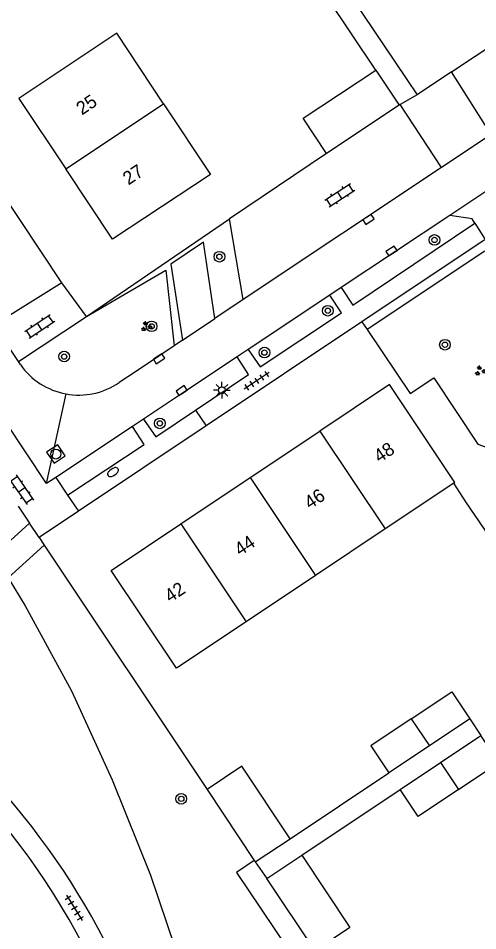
# Model space of a CAD drawing. Extents: x 137999 to 141000, y 397500 to 400501.
# Drawn here: x 138262.5 to 138297, y 399633.1 to 399701.6 of the extents above; entities that cross this region are included whole.
import ezdxf

# ---------------------------------------------------------------- set-up
doc = ezdxf.new("R2010")
doc.units = 0
for name, color, linetype in [('gg-afsc-erfafscheiding', 7, 'Continuous'), ('gg-afsc-muur', 7, 'Continuous'), ('gg-anno-huisnummerreeks BGT', 7, 'Continuous'), ('gg-bbg-bijgebouw', 7, 'Continuous'), ('gg-bbg-gedigitaliseerde bijgebouw', 7, 'Continuous'), ('gg-bbg-hoofdgebouw', 7, 'Continuous'), ('gg-bbg-tussenscheiding', 7, 'Continuous'), ('gg-knt-verharding', 7, 'Continuous'), ('gg-knt-verharding nz', 7, 'Continuous'), ('gt-grn-groengrens', 7, 'Continuous'), ('gt-grn-weggrens', 7, 'Continuous'), ('gt-symb-boom', 7, 'Continuous'), ('gt-symb-brandkraan', 7, 'Continuous'), ('gt-symb-groenvak', 7, 'Continuous'), ('gt-symb-klinker verharding', 7, 'Continuous'), ('gt-symb-kolk', 7, 'Continuous'), ('gt-symb-lichtmast', 7, 'Continuous'), ('gt-symb-rioolschacht', 7, 'Continuous'), ('gt-symb-tegel verharding', 7, 'Continuous')]:
    doc.layers.add(name, color=color, linetype=linetype)

# ---------------------------------------------------------------- blocks, each defined once
blk = doc.blocks.new('gt0-BOOM')
at = {"layer": 'gt-symb-boom'}
for radius in [0.4, 0.2]:
    blk.add_circle((0, 0), radius, dxfattribs=at)
blk = doc.blocks.new('gt0-TEG1')
at = {"layer": 'gt-symb-tegel verharding'}
for p, q in [((-1.125, 0), (1.125, 0)), ((-0.9, -0.25), (-0.9, 0.25)), ((-0.45, -0.25), (-0.45, 0.25)), ((0, -0.25), (0, 0.25)), ((0.45, -0.25), (0.45, 0.25)), ((0.9, -0.25), (0.9, 0.25))]:
    blk.add_line(p, q, dxfattribs=at)
blk = doc.blocks.new('gt0-KOLK')
at = {"layer": 'gt-symb-kolk'}
blk.add_lwpolyline([(0, 0), (0.375, 0), (0.375, 0.4), (-0.375, 0.4), (-0.375, 0), (0, 0)], dxfattribs=at)
blk = doc.blocks.new('gt0-KL1')
at = {"layer": 'gt-symb-klinker verharding'}
for p, q in [((-1.15, 0.3), (1.15, 0.3)), ((-1, -0.3), (-1, 0.3)), ((-0.5, 0.3), (-0.5, 0.45)), ((0, -0.3), (0, 0.3)), ((0.5, 0.3), (0.5, 0.45)), ((1, -0.3), (1, 0.3)), ((-1.15, -0.3), (1.15, -0.3)), ((-0.5, -0.45), (-0.5, -0.3)), ((0.5, -0.45), (0.5, -0.3))]:
    blk.add_line(p, q, dxfattribs=at)
blk = doc.blocks.new('gt0-GRVAK')
at = {"layer": 'gt-symb-groenvak'}
for p, q in [((-0.11, 0.189), (-0.228, 0.24)), ((-0.182, 0.153), (0.088, 0.153)), ((-0.091, 0.211), (-0.156, 0.322)), ((-0.047, 0.214), (-0.047, 0.393)), ((-0.004, 0.211), (0.061, 0.322)), ((0.015, 0.189), (0.133, 0.24)), ((0.262, -0.052), (0.197, 0.059)), ((0.305, -0.049), (0.305, 0.13)), ((0.349, -0.052), (0.414, 0.059)), ((-0.245, -0.228), (-0.363, -0.177)), ((-0.318, -0.264), (-0.047, -0.264)), ((-0.226, -0.206), (-0.291, -0.095)), ((-0.183, -0.203), (-0.183, -0.024)), ((-0.139, -0.206), (-0.074, -0.095)), ((-0.12, -0.228), (-0.002, -0.177)), ((0.243, -0.074), (0.125, -0.023)), ((0.17, -0.11), (0.441, -0.11)), ((0.368, -0.074), (0.486, -0.023))]:
    blk.add_line(p, q, dxfattribs=at)
blk = doc.blocks.new('gt0-LMAST')
at = {"layer": 'gt-symb-lichtmast'}
for p, q in [((-0.182, 0.173), (-0.447, 0.438)), ((-0.005, 0.246), (-0.005, 0.621)), ((0.172, 0.173), (0.437, 0.438)), ((-0.255, -0.004), (-0.63, -0.004)), ((-0.182, -0.181), (-0.447, -0.446)), ((-0.005, -0.254), (-0.005, -0.629)), ((0.437, -0.446), (0.172, -0.181)), ((0.245, -0.004), (0.62, -0.004))]:
    blk.add_line(p, q, dxfattribs=at)
blk.add_circle((-0.005, -0.004), 0.25, dxfattribs=at)
blk = doc.blocks.new('gt0-BR')
at = {"layer": 'gt-symb-brandkraan'}
for centre, radius, start, end in [((-0.244, 0), 0.206, 107.56694, 252.43307), ((0.599, -2.664), 3, 106.89205, 107.56694), ((0, -0.691), 0.938, 73.10799, 106.89205), ((-0.599, -2.664), 3, 72.43309, 73.10799), ((0.244, 0), 0.206, 287.56695, 72.43309), ((0.599, 2.664), 3, 252.43307, 253.10797), ((0, 0.691), 0.938, 253.10797, 286.89206), ((-0.599, 2.664), 3, 286.89206, 287.56695)]:
    blk.add_arc(centre, radius, start, end, dxfattribs=at)
blk = doc.blocks.new('gt0-RS')
at = {"layer": 'gt-symb-rioolschacht'}
blk.add_lwpolyline([(-0.5, -0.5), (0.5, -0.5), (0.5, 0.5), (-0.5, 0.5)], close=True, dxfattribs=at)
blk.add_circle((0, 0), 0.375, dxfattribs=at)

msp = doc.modelspace()

# ---------------------------------------------------------------- linework, layer by layer
at = {"layer": 'gg-afsc-erfafscheiding'}
for p, q in [((138279.828, 399714.694), (138292.482, 399695.837)), ((138289.392, 399697.691), (138281.769, 399709.098)), ((138295.071, 399697.548), (138301.085, 399701.579)), ((138265.82, 399681.726), (138258.009, 399693.444)), ((138267.677, 399679.192), (138278.393, 399686.523)), ((138300.604, 399658.7), (138296.142, 399665.293)), ((138264.11, 399662.61), (138264.5, 399662.025)), ((138264.5, 399662.025), (138276.72, 399643.68)), ((138296.438, 399648.991), (138297.27, 399647.743)), ((138282.96, 399640), (138290.374, 399644.946)), ((138283.82, 399638.77), (138291.207, 399643.698))]:
    msp.add_line(p, q, dxfattribs=at)
at = {"layer": 'gg-afsc-muur'}
msp.add_line((138296.142, 399665.293), (138295.24, 399666.683), dxfattribs=at)
at = {"layer": 'gg-bbg-bijgebouw'}
for p, q in [((138289.392, 399697.691), (138291.137, 399695.051)), ((138291.137, 399695.051), (138285.673, 399691.439)), ((138276.72, 399643.68), (138280.263, 399638.366)), ((138280.34, 399638.25), (138282.96, 399640)), ((138280.263, 399638.366), (138280.34, 399638.25)), ((138281.2, 399637.02), (138283.82, 399638.77)), ((138284.82, 399631.59), (138281.2, 399637.02))]:
    msp.add_line(p, q, dxfattribs=at)
for points in [[(138285.673, 399691.439), (138283.928, 399694.079), (138289.392, 399697.691)], [(138282.96, 399640), (138279.34, 399645.43), (138276.72, 399643.68)], [(138283.82, 399638.77), (138287.44, 399633.341), (138284.82, 399631.59)]]:
    msp.add_lwpolyline(points, dxfattribs=at)
at = {"layer": 'gg-bbg-gedigitaliseerde bijgebouw'}
for p, q in [((138296.438, 399648.991), (138293.406, 399646.969)), ((138294.239, 399645.721), (138297.27, 399647.743)), ((138293.406, 399646.969), (138290.374, 399644.946)), ((138291.207, 399643.698), (138294.239, 399645.721))]:
    msp.add_line(p, q, dxfattribs=at)
for points in [[(138292.05, 399649.001), (138295.082, 399651.024), (138296.438, 399648.991)], [(138292.05, 399649.001), (138289.018, 399646.979), (138290.374, 399644.946)], [(138295.594, 399643.688), (138298.626, 399645.711), (138297.27, 399647.743)], [(138295.594, 399643.688), (138292.563, 399641.665), (138291.207, 399643.698)]]:
    msp.add_lwpolyline(points, dxfattribs=at)
at = {"layer": 'gg-bbg-hoofdgebouw'}
for p, q in [((138279.964, 399667.11), (138285.181, 399670.594)), ((138274.747, 399663.625), (138279.964, 399667.11)), ((138295.24, 399666.683), (138290.088, 399663.246)), ((138290.088, 399663.246), (138284.869, 399659.765)), ((138284.869, 399659.765), (138279.65, 399656.283))]:
    msp.add_line(p, q, dxfattribs=at)
for points in [[(138273.458, 399695.168), (138269.95, 399700.47), (138262.59, 399695.56), (138266.11, 399690.275)], [(138273.458, 399695.168), (138276.97, 399689.86), (138269.63, 399684.99), (138266.11, 399690.275)], [(138295.24, 399666.683), (138295.31, 399666.73), (138290.4, 399674.08), (138285.181, 399670.594)], [(138279.65, 399656.283), (138274.43, 399652.8), (138269.53, 399660.14), (138274.747, 399663.625)]]:
    msp.add_lwpolyline(points, dxfattribs=at)
at = {"layer": 'gg-bbg-tussenscheiding'}
for p, q in [((138266.11, 399690.275), (138273.458, 399695.168)), ((138285.181, 399670.594), (138290.088, 399663.246)), ((138279.964, 399667.11), (138284.869, 399659.765)), ((138274.747, 399663.625), (138279.65, 399656.283)), ((138292.05, 399649.001), (138293.406, 399646.969)), ((138294.239, 399645.721), (138295.594, 399643.688))]:
    msp.add_line(p, q, dxfattribs=at)
at = {"layer": 'gg-knt-verharding'}
for p, q in [((138295.071, 399697.548), (138292.482, 399695.837)), ((138298.052, 399692.849), (138295.071, 399697.548)), ((138292.482, 399695.837), (138291.21, 399695.094)), ((138291.21, 399695.094), (138291.137, 399695.051)), ((138285.673, 399691.439), (138278.393, 399686.523)), ((138299.597, 399689.878), (138294.936, 399686.778)), ((138294.936, 399686.778), (138286.795, 399681.365)), ((138279.427, 399680.475), (138278.393, 399686.523)), ((138296.826, 399686.194), (138297.603, 399684.978)), ((138297.603, 399684.978), (138288.335, 399678.789)), ((138265.82, 399681.726), (138261.479, 399679.007)), ((138267.677, 399679.192), (138265.82, 399681.726)), ((138286.795, 399681.365), (138285.941, 399680.796)), ((138285.941, 399680.796), (138279.801, 399676.713)), ((138279.427, 399680.475), (138277.302, 399679.046)), ((138262.559, 399675.804), (138260.32, 399679.178)), ((138262.559, 399675.804), (138267.677, 399679.192)), ((138288.335, 399678.789), (138276.657, 399670.989)), ((138288.335, 399678.789), (138288.726, 399678.208)), ((138274.873, 399677.412), (138274.257, 399676.998)), ((138274.257, 399676.998), (138273.105, 399676.226)), ((138279.801, 399676.713), (138278.968, 399676.159)), ((138273.105, 399676.226), (138271.345, 399675.045)), ((138278.968, 399676.159), (138274.959, 399673.494)), ((138262.701, 399675.589), (138262.559, 399675.804)), ((138271.345, 399675.045), (138270.12, 399674.23)), ((138274.959, 399673.494), (138271.94, 399671.487)), ((138264.67, 399666.65), (138261.607, 399671.274)), ((138271.94, 399671.487), (138271.126, 399670.943)), ((138271.126, 399670.943), (138265.354, 399667.104)), ((138276.657, 399670.989), (138267.068, 399664.585)), ((138265.354, 399667.104), (138264.67, 399666.65)), ((138265.354, 399667.104), (138266.249, 399665.789)), ((138266.249, 399665.789), (138267.068, 399664.585)), ((138262.53, 399664.96), (138263.377, 399663.687)), ((138267.068, 399664.585), (138264.11, 399662.61)), ((138264.11, 399662.61), (138263.377, 399663.687))]:
    msp.add_line(p, q, dxfattribs=at)
for points in [[(138296.826, 399686.194), (138296.614, 399686.527), (138294.936, 399686.778)], [(138286.795, 399681.365), (138287.66, 399680.037), (138296.826, 399686.194)], [(138277.302, 399679.046), (138276.444, 399684.779), (138274.007, 399683.116), (138274.873, 399677.412)], [(138279.801, 399676.713), (138280.694, 399675.406), (138286.821, 399679.474), (138285.941, 399680.796)], [(138288.726, 399678.208), (138291.961, 399673.402), (138293.735, 399674.587), (138297.034, 399669.599), (138299.834, 399668.609), (138304.044, 399671.423)], [(138275.856, 399672.169), (138279.838, 399674.846), (138278.968, 399676.159)], [(138271.94, 399671.487), (138272.862, 399670.155), (138275.856, 399672.169)], [(138266.249, 399665.789), (138271.999, 399669.586), (138271.126, 399670.943)], [(138251.89, 399653.84), (138253.98, 399655.46), (138261.39, 399661.86), (138263.377, 399663.687)], [(138280.263, 399638.366), (138278.92, 399637.45), (138295.797, 399612.392)]]:
    msp.add_lwpolyline(points, dxfattribs=at)
for centre, radius, start, end in [((138267.098, 399678.661), 5.363, 214.9381, 259.61509), ((138267.098, 399678.66), 5.362, 259.61485, 304.30575), ((138219.04, 399606.399), 56.328, 9.83485, 42.9859), ((138219.172, 399606.801), 54.43, 5.40396, 42.76728)]:
    msp.add_arc(centre, radius, start, end, dxfattribs=at)
at = {"layer": 'gg-knt-verharding nz'}
for p, q in [((138294.326, 399690.374), (138291.21, 399695.094)), ((138298.052, 399692.849), (138294.326, 399690.374)), ((138294.326, 399690.374), (138279.427, 399680.475)), ((138274.873, 399677.412), (138277.302, 399679.046))]:
    msp.add_line(p, q, dxfattribs=at)
at = {"layer": 'gt-grn-groengrens'}
msp.add_line((138297.561, 399684.108), (138288.726, 399678.208), dxfattribs=at)
for points in [[(138267.677, 399679.192), (138273.628, 399682.66), (138274.257, 399676.998)], [(138264.5, 399662.025), (138261.778, 399659.59), (138263.061, 399657.468), (138266.533, 399651.108), (138269.583, 399644.426), (138272.462, 399637.262), (138274.919, 399630.017), (138277.375, 399621.484), (138277.036, 399619.552), (138275.815, 399617.461), (138285.981, 399610.105), (138292.444, 399611.469), (138295.797, 399612.392)]]:
    msp.add_lwpolyline(points, dxfattribs=at)
at = {"layer": 'gt-grn-weggrens'}
for p, q in [((138264.67, 399666.65), (138266.131, 399673.385)), ((138275.856, 399672.169), (138276.657, 399670.989)), ((138280.34, 399638.25), (138281.2, 399637.02))]:
    msp.add_line(p, q, dxfattribs=at)

# ---------------------------------------------------------------- block references
at = {"layer": 'gt-symb-boom'}
for p in [(138293.79, 399684.936), (138277.646, 399683.681), (138285.78, 399679.627), (138272.553, 399678.455), (138294.577, 399677.078), (138265.993, 399676.187), (138281.025, 399676.486), (138273.169, 399671.169), (138274.779, 399642.987)]:
    msp.add_blockref('gt0-BOOM', p, dxfattribs=at)
at = {"layer": 'gt-symb-brandkraan', "rotation": 33.70595653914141}
msp.add_blockref('gt0-BR', (138269.656, 399667.516), dxfattribs=at)
at = {"layer": 'gt-symb-groenvak'}
for p in [(138272.148, 399678.438), (138297.215, 399675.111)]:
    msp.add_blockref('gt0-GRVAK', p, dxfattribs=at)
at = {"layer": 'gt-symb-klinker verharding'}
for p, rotation in [((138286.675, 399688.306), 32.87978190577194), ((138264.16, 399678.448), 33.83302869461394), ((138262.792, 399666.19), -55.18164551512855)]:
    msp.add_blockref('gt0-KL1', p, dxfattribs=dict(at, rotation=rotation))
at = {"layer": 'gt-symb-kolk'}
for p, rotation in [((138288.73, 399686.65), -146.37347087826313), ((138290.669, 399683.942), 33.626529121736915), ((138273.005, 399676.185), -146.96171538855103), ((138274.92, 399673.466), 33.626529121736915)]:
    msp.add_blockref('gt0-KOLK', p, dxfattribs=dict(at, rotation=rotation))
at = {"layer": 'gt-symb-lichtmast'}
msp.add_blockref('gt0-LMAST', (138277.841, 399673.66), dxfattribs=at)
at = {"layer": 'gt-symb-rioolschacht', "rotation": 33.62652912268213}
msp.add_blockref('gt0-RS', (138265.368, 399668.87), dxfattribs=at)
at = {"layer": 'gt-symb-tegel verharding'}
for p, rotation in [((138280.449, 399674.368), -146.5005999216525), ((138266.748, 399634.806), -58.5351269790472)]:
    msp.add_blockref('gt0-TEG1', p, dxfattribs=dict(at, rotation=rotation))

# ---------------------------------------------------------------- texts
at = {"layer": 'gg-anno-huisnummerreeks BGT'}
for s, p in [('25', (138267.32, 399694.272)), ('27', (138270.818, 399689.02)), ('48', (138289.657, 399668.173)), ('46', (138284.439, 399664.688)), ('44', (138279.193, 399661.184)), ('42', (138273.949, 399657.681))]:
    msp.add_text(s, height=1, rotation=33.7, dxfattribs=at).set_placement(p)

doc.saveas('drawing.dxf')
